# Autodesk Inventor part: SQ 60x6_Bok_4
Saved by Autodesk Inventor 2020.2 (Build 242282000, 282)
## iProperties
Created: 2006-08
Part Number: SQ 60x6_Bok_4
Material: Ogólny
Document SubType Name: Modeling
Designer: F.Stasiak
Manufacturer: Standard
Standards Organization: Custom
Stock Number: DIN EN 10210-2 SQ 60x6
Density: 1 g/cm^3
Appearance: Domyślna
Manager: www.cadconsulting.pl
Company: Fabian Stasiak CAD Consulting
G_L: 767,1 mm
G_W: 60,000 mm
G_H: 60,000 mm
AFG_Item: 60 x 60 x 6
Author: F.Stasiak
Subject: Zbiór ćwiczeń. Autodesk Inventor 2020. Kurs podstawowy
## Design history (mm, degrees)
sketch "AFG_Detailed"
  geometry: L1 (-12, -6)-(-48, -6); L2 (-54, -12)-(-54, -48); L3 (-48, -54)-(-12, -54); L4 (-6, -48)-(-6, -12); L5 (-12, 0)-(-48, 0); L6 (-60, -12)-(-60, -48); L7 (-48, -60)-(-12, -60); L8 (0, -48)-(0, -12); A1 r 6 centre (-12, -12) between (-6, -12) and (-12, -6); A2 r 12 centre (-12, -12) between (0, -12) and (-12, 0); A3 r 6 centre (-12, -48) between (-12, -54) and (-6, -48); A4 r 12 centre (-12, -48) between (-12, -60) and (0, -48); A5 r 12 centre (-48, -48) between (-60, -48) and (-48, -60); A6 r 6 centre (-48, -48) between (-54, -48) and (-48, -54); A7 r 6 centre (-48, -12) between (-48, -6) and (-54, -12); A8 r 12 centre (-48, -12) between (-48, 0) and (-60, -12); 4 further points
  constraints: 16 end point, 16 point on circle, 16 tangent, 8 centre point, 6 point on line, 4 parallel, 2 perpendicular, 1 vertical
  dimensions: "d15" = 60 distance of point (-60, -60) point (0, -60) (= GEO_B); "d16" = 6 distance between parallel lines of L7 L3 (= GEO_S); "d17" = 6 distance between parallel lines of L8 L4 (= GEO_S); "d18" = 6 distance between parallel lines of L5 L1 (= GEO_S); "d19" = 6 distance between parallel lines of L6 L2 (= GEO_S); "d20" = 30 distance from line of point (-30, -30) L7 (= 0.5 x GEO_H); "d30" = 6 radius of A1 (= GEO_R1 - GEO_S); "GEO_R1" = 12 radius of A2; "d32" = 6 radius of A3 (= GEO_R1 - GEO_S); "d33" = 12 radius of A4 (= GEO_R1); "d34" = 12 radius of A5 (= GEO_R1); "d35" = 6 radius of A6 (= GEO_R1 - GEO_S); "d36" = 6 radius of A7 (= GEO_R1 - GEO_S); "d37" = 12 radius of A8 (= GEO_R1); "d38" = 30 distance from line of L6 point (-30, -30) (= 0.5 x GEO_B); "d39" = 60 distance between parallel lines of L7 L5 (= GEO_H)
sketch "AFG_Medium"
  geometry: L1 (-6, -6)-(-54, -6); L2 (-54, -6)-(-54, -54); L3 (-54, -54)-(-6, -54); L4 (-6, -54)-(-6, -6); L5 (0, 0)-(-60, 0); L6 (-60, 0)-(-60, -60); L7 (-60, -60)-(0, -60); L8 (0, -60)-(0, 0); 1 further point
  constraints: 16 end point, 4 parallel, 2 perpendicular, 1 vertical
  dimensions: "GEO_B" = 60 distance of L6.end L7.end; "GEO_S" = 6 distance between parallel lines of L7 L3; "d5" = 6 distance between parallel lines of L8 L4 (= GEO_S); "d6" = 6 distance between parallel lines of L5 L1 (= GEO_S); "d7" = 6 distance between parallel lines of L6 L2 (= GEO_S); "d12" = 30 distance from line of point (-30, -30) L7 (= 0.5 x GEO_H); "d40" = 60 distance between parallel lines of L7 L5 (= GEO_H); "d41" = 30 distance from line of L6 point (-30, -30) (= 0.5 x GEO_B)
sketch "AFG_Simplified"
  geometry: L1 (0, 0)-(-60, 0); L2 (-60, 0)-(-60, -60); L3 (-60, -60)-(0, -60); L4 (0, -60)-(0, 0); 1 further point
  constraints: 8 end point, 2 parallel, 1 perpendicular, 1 vertical
  dimensions: "d23" = 60 distance of L2.end L3.end (= GEO_B); "d28" = 30 distance from line of point (-30, -30) L3 (= 0.5 x GEO_H); "d42" = 60 distance between parallel lines of L3 L1 (= GEO_H); "d43" = 30 distance from line of point (-30, -30) L2 (= 0.5 x GEO_B)
derived "Szkielet podstawy.ipt"
  sketch "Szkic1"
    geometry: L1 (0, 0)-(1500, 0) reference; L2 (1500, 0)-(1500, 1000) reference; L3 (1500, 1000)-(0, 1000) reference; L4 (0, 1000)-(0, 0) reference
  sketch "Szkic2"
    geometry: L1 (0, 1000)-(0, 0) reference; L2 (0, 0)-(1500, 0) reference; L3 (1500, 0)-(1500, 1000) reference; L4 (500, 1000)-(1500, 1000) reference; L5 (1500, 1000)-(1500, 0) reference; L6 (1500, 0)-(500, 0) reference; L7 (500, 0)-(500, 1000) reference; L8 (1500, 1000)-(0, 1000) reference
node "AFG_StartWorkPoint_SQ 60x6_Bok_4"
node "AFG_EndWorkPoint_SQ 60x6_Bok_4"
node "AFG_HelpAxis"
node "AFG_HelpStart"
node "AFG_HelpEnd"
node "AFG_Midplane"
  node "AFG_Startplane"
  node "AFG_EndPlane"
node "AFG_Profile_AxisX_for_External_Matrix"
node "SQ 60x6_Spód_4" dims "d53" = 10
node "SQ 60x6_Góra_4" dims "d55" = 10
extrude "AFG_Detailed_SQ 60x6_Bok_4" join sketch "AFG_Detailed" stored distance "d49" = 0.13; taper "d50" = 0 deg
extrude "AFG_Simplified_SQ 60x6_Bok_4" join sketch "AFG_Simplified" stored distance "d51" = 0.13; taper "d52" = 0 deg
node "AFG_STARTCUTPLANE_SQ 60x6_Bok_4"
node "AFG_ENDCUTPLANE_SQ 60x6_Bok_4"
node "Bryła1"
node "Korpusy bryłowe"
node "Korpusy powierzchniowe"
feature "Pozyskana bryła konstrukcyjna1"
body "Srf1"
feature "Pozyskana bryła konstrukcyjna2"
body "Srf2"
feature "DerivedBody::SQ 60x6_Spód_4"
feature "DerivedBody::SQ 60x6_Góra_4"
other parameters: "GEO_H" = 60, "AFG_Origin_X" = 0 (= 0 x GEO_B) [user parameter], "AFG_Origin_Y" = 0 (= 0 x GEO_H) [user parameter], "AFG_IP_X2" = 0 (= 0 x GEO_B) [user parameter], "AFG_IP_Y4" = 0 (= 0 x GEO_H) [user parameter], "AFG_IP_X6" = 0 (= 0 x GEO_B) [user parameter], "AFG_IP_Y8" = 0 (= 0 x GEO_H) [user parameter], "d47" = 0, "d48" = 0, "G_L" = 767.10678 [user parameter], "d54" = 0, "d56" = 0
